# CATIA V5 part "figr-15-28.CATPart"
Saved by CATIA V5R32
Part number: Part1
Bounding box of the stored display mesh (mm): x -61.282 to 61.282, y -26.72 to 26.72, z 0 to 45.75
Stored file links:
  D:\PROJECTS\Project 2022\CATIA V5 6R 2022\Resources\Part Files\c15_catia_v5_6r2022_prt\figr-15-28.CATPart
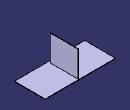
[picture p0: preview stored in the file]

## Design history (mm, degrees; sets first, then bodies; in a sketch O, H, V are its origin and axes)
SheetMetalParameters1: Thickness 0.75, BendRadius 1, KFactor 0.356492 {= log(min(100,max(20*SheetMetalParameters1.BendRadius,SheetMetalParameters1.Thickness)/SheetMetalParameters1.Thickness))/log(100)/2}, ReliefRadialLength 1, ReliefAxialLength 2, MinimumBendRadius 0
Body1 (main body)
  Sketch1 on xy-plane, origin (0, 0, 0), H (1, 0, 0), V (0, 1, 0)
    line L1 (61.282, 26.7197) -> (61.282, -26.7197)
    line L2 (61.282, -26.7197) -> (-61.282, -26.7197)
    line L3 (-61.282, -26.7197) -> (-61.282, 26.7197)
    line L4 (-61.282, 26.7197) -> (61.282, 26.7197)
    vertical: L1 V, L3 V
    horizontal: L2 H, L4 H
    equidistance: L1 L3 O, L2 L4 O
  Wall1: Thickness 0.75, Profile Sketch1
  Sketch2 on face of Wall1, origin (0, 0, 0.75), H (1, 0, 0), V (0, 1, 0)
    line L1 (1.9015, 25.4615) -> (1.9015, -22.9675)
    vertical: L1 V
  d_Extrude1: Extrude_Thickness 0.75, Extrude_Profile Sketch2, Extrude_StartLength 45, Extrude_EndLength 0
